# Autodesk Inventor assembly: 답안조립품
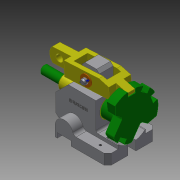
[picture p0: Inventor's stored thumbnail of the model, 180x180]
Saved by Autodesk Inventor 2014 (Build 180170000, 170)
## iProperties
Created: 2016-11
Part Number: 답안조립품
Document SubType Name: Assembly
Designer: user
Author: user
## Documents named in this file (8)
- C:\Users\user\Desktop\461108V1003\답안조립품.iam
- C:\Users\user\Desktop\461108V1003\본체.ipt
- C:\Users\user\Desktop\461108V1003\부시.ipt
- C:\Users\user\Desktop\461108V1003\분할축.ipt
- C:\Users\user\Desktop\461108V1003\분할대.ipt
- C:\Users\user\Desktop\461108V1003\클레비스핀.ipt
- C:\Users\user\Desktop\461108V1003\와셔.ipt
- C:\Users\user\Desktop\461108V1003\원통형핀.ipt
